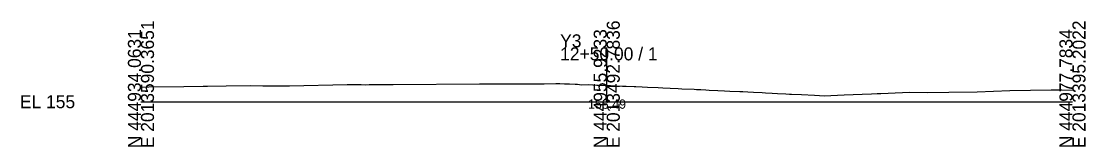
# Model space of a CAD drawing. Extents: x -26 to 203, y -10 to 5017.
# Drawn here: x -25.7 to 202.8, y 4990.3 to 5017.3 of the extents above; entities that cross this region are included whole.
import ezdxf

# ---------------------------------------------------------------- set-up
doc = ezdxf.new("R2010")
doc.units = 0
for name, color, linetype in [('Exist Cross Section Cell', 7, 'Continuous'), ('Exist XS Center Line Elevation Label', 7, 'Continuous'), ('Exist XS Ground Line', 7, 'Continuous')]:
    doc.layers.add(name, color=color, linetype=linetype)

msp = doc.modelspace()

# ---------------------------------------------------------------- linework, layer by layer
at = {"layer": 'Exist Cross Section Cell'}
for p, q in [((100, 5000), (100, 5011.7)), ((0, 5000), (100, 5000)), ((100, 5000), (200, 5000))]:
    msp.add_line(p, q, dxfattribs=at)
at = {"layer": 'Exist XS Ground Line'}
msp.add_lwpolyline([(0, 5003.13), (1.71, 5003.17), (9.23, 5003.29), (13.33, 5003.33), (14.27, 5003.38), (18.31, 5003.43), (23.48, 5003.47), (26.16, 5003.42), (31.91, 5003.44), (44.29, 5003.7), (45.25, 5003.71), (47.31, 5003.71), (48.16, 5003.66), (48.98, 5003.69), (53.49, 5003.74), (53.8, 5003.74), (54.16, 5003.74), (72.69, 5003.82), (73.53, 5003.82), (74.44, 5003.82), (75.43, 5003.82), (76.53, 5003.83), (77.76, 5003.83), (79.12, 5003.84), (80.65, 5003.85), (82.38, 5003.86), (84.35, 5003.87), (86.57, 5003.88), (89.07, 5003.9), (89.93, 5003.9), (90.94, 5003.86), (92.03, 5003.82), (93.21, 5003.78), (93.75, 5003.76), (94.61, 5003.62), (96.13, 5003.67), (97.85, 5003.58), (98.23, 5003.57), (100, 5003.49), (100.8, 5003.46), (102.05, 5003.41), (103.36, 5003.36), (104.14, 5003.33), (105.92, 5003.26), (106.23, 5003.25), (107.61, 5003.19), (108.75, 5003.14), (111.05, 5003.03), (112.05, 5002.99), (113.61, 5002.92), (115.35, 5002.83), (116.16, 5002.8), (118.81, 5002.68), (119.29, 5002.66), (119.63, 5002.64), (120.21, 5002.61), (121.28, 5002.55), (121.96, 5002.52), (123.84, 5002.42), (125.27, 5002.35), (126.4, 5002.3), (128.59, 5002.2), (129.2, 5002.17), (130.27, 5002.12), (131.53, 5002.06), (133.39, 5001.96), (134.09, 5001.92), (135.5, 5001.85), (136.65, 5001.79), (138.49, 5001.69), (139.22, 5001.66), (139.68, 5001.63), (141.79, 5001.52), (144.63, 5001.39), (145.7, 5001.34), (146.68, 5001.29), (150.98, 5001.47), (154.84, 5001.63), (156.84, 5001.71), (158.07, 5001.76), (158.88, 5001.79), (163.49, 5002), (165.05, 5002.03), (168.81, 5002.01), (173.44, 5002.09), (179.51, 5002.14), (186.58, 5002.4), (195.45, 5002.53), (197.69, 5002.53), (200, 5002.47)], dxfattribs=at)

# ---------------------------------------------------------------- texts
at = {"layer": 'Exist Cross Section Cell'}
for s, p in [('E 2013590.3651', (2.8, 4990)), ('E 2013492.7836', (102.8, 4990)), ('E 2013395.2022', (202.8, 4990)), ('N 444934.0631', (0, 4990)), ('N 444955.9233', (100, 4990)), ('N 444977.7834', (200, 4990))]:
    msp.add_text(s, height=2.8, rotation=90, dxfattribs=at).set_placement(p)
for s, p in [('Y3', (90, 5011.7)), ('12+50.00 / 1', (90, 5008.9)), ('EL 155', (-26, 4998.6))]:
    msp.add_text(s, height=2.8, dxfattribs=at).set_placement(p)
at = {"layer": 'Exist XS Center Line Elevation Label'}
msp.add_text('158.49', height=2, dxfattribs=at).set_placement((95.97, 4998.49))

doc.saveas('drawing.dxf')
